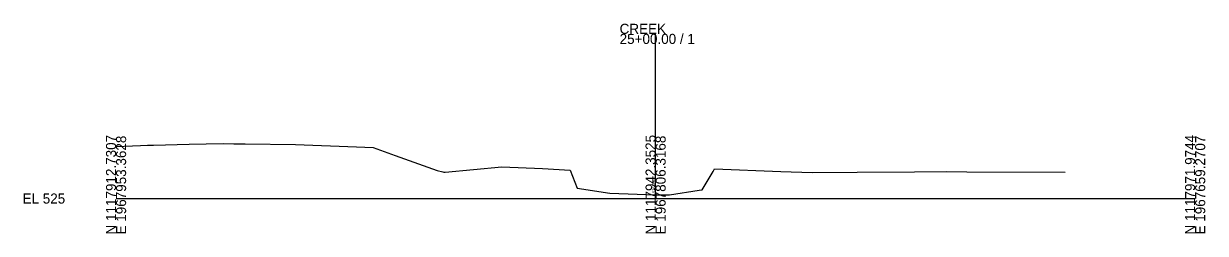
# Model space of a CAD drawing. Extents: x 9974 to 10303, y 9990 to 19550.
# Drawn here: x 9974.3 to 10302.8, y 13990.3 to 14048.6 of the extents above; entities that cross this region are included whole.
import ezdxf

# ---------------------------------------------------------------- set-up
doc = ezdxf.new("R2010")
doc.units = 0
for name, color, linetype in [('Level 10', 7, 'Continuous'), ('Level 60', 7, 'Continuous'), ('Level 63', 7, 'Continuous')]:
    doc.layers.add(name, color=color, linetype=linetype)

msp = doc.modelspace()

# ---------------------------------------------------------------- linework, layer by layer
at = {"layer": 'Level 60'}
for p, q in [((10020.32, 14015.07), (10029.79, 14015.26)), ((10029.79, 14015.26), (10032.76, 14015.25)), ((10032.76, 14015.25), (10035.28, 14015.23)), ((10035.28, 14015.23), (10035.93, 14015.21)), ((10035.93, 14015.21), (10049.93, 14015.01)), ((10000, 14014.5), (10006.76, 14014.74)), ((10006.76, 14014.74), (10008.76, 14014.81)), ((10008.76, 14014.81), (10010.43, 14014.85)), ((10010.43, 14014.85), (10020.32, 14015.07)), ((10049.93, 14015.01), (10066.87, 14014.41)), ((10066.87, 14014.41), (10071.48, 14014.15)), ((10071.48, 14014.15), (10077.62, 14011.98)), ((10077.62, 14011.98), (10089.3, 14007.77)), ((10091.53, 14007.36), (10107.27, 14008.85)), ((10107.27, 14008.85), (10118.6, 14008.36)), ((10089.3, 14007.77), (10090.86, 14007.45)), ((10090.86, 14007.45), (10091.09, 14007.3)), ((10091.09, 14007.3), (10091.53, 14007.36)), ((10118.6, 14008.36), (10126.21, 14007.86)), ((10126.21, 14007.86), (10128.2, 14002.87)), ((10162.99, 14002.37), (10165.96, 14007.54)), ((10165.96, 14007.54), (10166.38, 14008.29)), ((10166.38, 14008.29), (10184.79, 14007.55)), ((10184.79, 14007.55), (10193.57, 14007.25)), ((10193.57, 14007.25), (10206.07, 14007.3)), ((10206.07, 14007.3), (10222.02, 14007.38)), ((10222.02, 14007.38), (10230.82, 14007.49)), ((10230.82, 14007.49), (10236.51, 14007.46)), ((10236.51, 14007.46), (10263.87, 14007.29)), ((10128.2, 14002.87), (10137.32, 14001.46)), ((10153.87, 14001.02), (10162.11, 14002.28)), ((10162.11, 14002.28), (10162.99, 14002.37)), ((10137.32, 14001.46), (10150, 14001.05)), ((10150, 14001.05), (10152.28, 14000.98)), ((10152.28, 14000.98), (10153.87, 14001.02))]:
    msp.add_line(p, q, dxfattribs=at)
at = {"layer": 'Level 63'}
for p, q in [((10150, 14000), (10150, 14045.79)), ((10000, 14000), (10150, 14000)), ((10150, 14000), (10300, 14000))]:
    msp.add_line(p, q, dxfattribs=at)

# ---------------------------------------------------------------- texts
at = {"layer": 'Level 10'}
msp.add_text('526.050', height=0.8, rotation=90, dxfattribs=at).set_placement((10149.9, 14001.55))
at = {"layer": 'Level 63'}
for s, p in [('CREEK', (10140, 14045.79)), ('25+00.00 / 1', (10140, 14042.99)), ('EL 525', (9974, 13998.6))]:
    msp.add_text(s, height=2.8, dxfattribs=at).set_placement(p)
for s, p in [('N 1117912.7307', (10000, 13990)), ('E 1967953.3628', (10002.8, 13990)), ('N 1117942.3525', (10150, 13990)), ('E 1967806.3168', (10152.8, 13990)), ('N 1117971.9744', (10300, 13990)), ('E 1967659.2707', (10302.8, 13990))]:
    msp.add_text(s, height=2.8, rotation=90, dxfattribs=at).set_placement(p)

doc.saveas('drawing.dxf')
